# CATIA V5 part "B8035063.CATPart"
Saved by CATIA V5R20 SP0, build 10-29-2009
Part number: B8035063
Revision: 5
Definition: design
Nomenclature: B8035063
Source: made
Description: NOT SPECIFIED
Bounding box of the stored display mesh (mm): x -35 to 35, y -35 to 35, z 0 to 63
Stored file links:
  C:\Users\Utente\Desktop\3D files B803\B8035063.CATPart
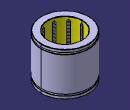
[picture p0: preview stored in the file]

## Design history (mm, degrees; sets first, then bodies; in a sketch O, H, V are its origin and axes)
Body1 "MANIFOLD_SOLID_BREP #38" (main body)
  Solid1: solid without history
Body2 "MANIFOLD_SOLID_BREP #76"
  Solid2: solid without history
Body3 "MANIFOLD_SOLID_BREP #114"
  Solid3: solid without history
Body4 "MANIFOLD_SOLID_BREP #152"
  Solid4: solid without history
Body5 "MANIFOLD_SOLID_BREP #190"
  Solid5: solid without history
Body6 "MANIFOLD_SOLID_BREP #228"
  Solid6: solid without history
Body7 "MANIFOLD_SOLID_BREP #266"
  Solid7: solid without history
Body8 "MANIFOLD_SOLID_BREP #304"
  Solid8: solid without history
Body9 "MANIFOLD_SOLID_BREP #2798"
  Solid9: solid without history
Body10 "MANIFOLD_SOLID_BREP #2836"
  Solid10: solid without history
Body11 "MANIFOLD_SOLID_BREP #2874"
  Solid11: solid without history
Body12 "MANIFOLD_SOLID_BREP #2912"
  Solid12: solid without history
Body13 "MANIFOLD_SOLID_BREP #2950"
  Solid13: solid without history
Body14 "MANIFOLD_SOLID_BREP #2988"
  Solid14: solid without history
Body15 "MANIFOLD_SOLID_BREP #3026"
  Solid15: solid without history
Body16 "MANIFOLD_SOLID_BREP #3064"
  Solid16: solid without history
Body17 "MANIFOLD_SOLID_BREP #3102"
  Solid17: solid without history
Body18 "MANIFOLD_SOLID_BREP #3140"
  Solid18: solid without history
Body19 "MANIFOLD_SOLID_BREP #3178"
  Solid19: solid without history
Body20 "MANIFOLD_SOLID_BREP #3216"
  Solid20: solid without history
Body21 "MANIFOLD_SOLID_BREP #3254"
  Solid21: solid without history
Body22 "MANIFOLD_SOLID_BREP #3292"
  Solid22: solid without history
Body23 "MANIFOLD_SOLID_BREP #3330"
  Solid23: solid without history
Body24 "MANIFOLD_SOLID_BREP #3368"
  Solid24: solid without history
Body25 "MANIFOLD_SOLID_BREP #3406"
  Solid25: solid without history
Body26 "MANIFOLD_SOLID_BREP #3444"
  Solid26: solid without history
Body27 "MANIFOLD_SOLID_BREP #3482"
  Solid27: solid without history
Body28 "MANIFOLD_SOLID_BREP #3520"
  Solid28: solid without history
Body29 "MANIFOLD_SOLID_BREP #3558"
  Solid29: solid without history
Body30 "MANIFOLD_SOLID_BREP #3596"
  Solid30: solid without history
Body31 "MANIFOLD_SOLID_BREP #3634"
  Solid31: solid without history
Body32 "MANIFOLD_SOLID_BREP #3672"
  Solid32: solid without history
Body33 "MANIFOLD_SOLID_BREP #3710"
  Solid33: solid without history
Body34 "MANIFOLD_SOLID_BREP #3748"
  Solid34: solid without history
Body35 "MANIFOLD_SOLID_BREP #3786"
  Solid35: solid without history
Body36 "MANIFOLD_SOLID_BREP #3824"
  Solid36: solid without history
Body37 "MANIFOLD_SOLID_BREP #3862"
  Solid37: solid without history
Body38 "MANIFOLD_SOLID_BREP #3900"
  Solid38: solid without history
Body39 "MANIFOLD_SOLID_BREP #3938"
  Solid39: solid without history
Body40 "MANIFOLD_SOLID_BREP #3976"
  Solid40: solid without history
Body41 "MANIFOLD_SOLID_BREP #4014"
  Solid41: solid without history
Body42 "MANIFOLD_SOLID_BREP #4052"
  Solid42: solid without history
Body43 "MANIFOLD_SOLID_BREP #4090"
  Solid43: solid without history
Body44 "MANIFOLD_SOLID_BREP #4128"
  Solid44: solid without history
Body45 "MANIFOLD_SOLID_BREP #4166"
  Solid45: solid without history
Body46 "MANIFOLD_SOLID_BREP #4204"
  Solid46: solid without history
Body47 "MANIFOLD_SOLID_BREP #4242"
  Solid47: solid without history
Body48 "MANIFOLD_SOLID_BREP #4280"
  Solid48: solid without history
Body49 "MANIFOLD_SOLID_BREP #4318"
  Solid49: solid without history
Body50 "MANIFOLD_SOLID_BREP #4356"
  Solid50: solid without history
Body51 "MANIFOLD_SOLID_BREP #4394"
  Solid51: solid without history
Body52 "MANIFOLD_SOLID_BREP #4432"
  Solid52: solid without history
Body53 "MANIFOLD_SOLID_BREP #4470"
  Solid53: solid without history
Body54 "MANIFOLD_SOLID_BREP #4508"
  Solid54: solid without history
Body55 "MANIFOLD_SOLID_BREP #4546"
  Solid55: solid without history
Body56 "MANIFOLD_SOLID_BREP #4584"
  Solid56: solid without history
Body57 "MANIFOLD_SOLID_BREP #4622"
  Solid57: solid without history
Body58 "MANIFOLD_SOLID_BREP #4660"
  Solid58: solid without history
Body59 "MANIFOLD_SOLID_BREP #4698"
  Solid59: solid without history
Body60 "MANIFOLD_SOLID_BREP #4736"
  Solid60: solid without history
Body61 "MANIFOLD_SOLID_BREP #4774"
  Solid61: solid without history
Body62 "MANIFOLD_SOLID_BREP #4812"
  Solid62: solid without history
Body63 "MANIFOLD_SOLID_BREP #4850"
  Solid63: solid without history
Body64 "MANIFOLD_SOLID_BREP #4888"
  Solid64: solid without history
Body65 "MANIFOLD_SOLID_BREP #4926"
  Solid65: solid without history
Body66 "MANIFOLD_SOLID_BREP #4964"
  Solid66: solid without history
Body67 "MANIFOLD_SOLID_BREP #5002"
  Solid67: solid without history
Body68 "MANIFOLD_SOLID_BREP #5040"
  Solid68: solid without history
Body69 "MANIFOLD_SOLID_BREP #5078"
  Solid69: solid without history
Body70 "MANIFOLD_SOLID_BREP #5116"
  Solid70: solid without history
Body71 "MANIFOLD_SOLID_BREP #5154"
  Solid71: solid without history
Body72 "MANIFOLD_SOLID_BREP #5192"
  Solid72: solid without history
Body73 "MANIFOLD_SOLID_BREP #5230"
  Solid73: solid without history
Body74 "MANIFOLD_SOLID_BREP #5268"
  Solid74: solid without history
Body75 "MANIFOLD_SOLID_BREP #5306"
  Solid75: solid without history
Body76 "MANIFOLD_SOLID_BREP #5344"
  Solid76: solid without history
Body77 "MANIFOLD_SOLID_BREP #5382"
  Solid77: solid without history
Body78 "MANIFOLD_SOLID_BREP #5420"
  Solid78: solid without history
Body79 "MANIFOLD_SOLID_BREP #5458"
  Solid79: solid without history
Body80 "MANIFOLD_SOLID_BREP #5496"
  Solid80: solid without history
Body81 "MANIFOLD_SOLID_BREP #5534"
  Solid81: solid without history
Body82 "MANIFOLD_SOLID_BREP #5572"
  Solid82: solid without history
Body83 "MANIFOLD_SOLID_BREP #5610"
  Solid83: solid without history
Body84 "MANIFOLD_SOLID_BREP #5648"
  Solid84: solid without history
Body85 "MANIFOLD_SOLID_BREP #5686"
  Solid85: solid without history
Body86 "MANIFOLD_SOLID_BREP #5724"
  Solid86: solid without history
Body87 "MANIFOLD_SOLID_BREP #5762"
  Solid87: solid without history
Body88 "MANIFOLD_SOLID_BREP #5800"
  Solid88: solid without history
Body89 "MANIFOLD_SOLID_BREP #5838"
  Solid89: solid without history
Body90 "MANIFOLD_SOLID_BREP #5876"
  Solid90: solid without history
Body91 "MANIFOLD_SOLID_BREP #5914"
  Solid91: solid without history
Body92 "MANIFOLD_SOLID_BREP #5952"
  Solid92: solid without history
Body93 "MANIFOLD_SOLID_BREP #5990"
  Solid93: solid without history
Body94 "MANIFOLD_SOLID_BREP #6028"
  Solid94: solid without history
Body95 "MANIFOLD_SOLID_BREP #6066"
  Solid95: solid without history
Body96 "MANIFOLD_SOLID_BREP #6104"
  Solid96: solid without history
Body97 "MANIFOLD_SOLID_BREP #6142"
  Solid97: solid without history
Body98 "MANIFOLD_SOLID_BREP #6180"
  Solid98: solid without history
Body99 "MANIFOLD_SOLID_BREP #6218"
  Solid99: solid without history
Body100 "MANIFOLD_SOLID_BREP #6256"
  Solid100: solid without history
Body101 "MANIFOLD_SOLID_BREP #6294"
  Solid101: solid without history
Body102 "MANIFOLD_SOLID_BREP #6332"
  Solid102: solid without history
Body103 "MANIFOLD_SOLID_BREP #6370"
  Solid103: solid without history
Body104 "MANIFOLD_SOLID_BREP #6408"
  Solid104: solid without history
Body105 "MANIFOLD_SOLID_BREP #6446"
  Solid105: solid without history
Body106 "MANIFOLD_SOLID_BREP #6484"
  Solid106: solid without history
Body107 "MANIFOLD_SOLID_BREP #6522"
  Solid107: solid without history
Body108 "MANIFOLD_SOLID_BREP #6560"
  Solid108: solid without history
Body109 "MANIFOLD_SOLID_BREP #6598"
  Solid109: solid without history
Body110 "MANIFOLD_SOLID_BREP #6636"
  Solid110: solid without history
Body111 "MANIFOLD_SOLID_BREP #6674"
  Solid111: solid without history
Body112 "MANIFOLD_SOLID_BREP #6712"
  Solid112: solid without history
Body113 "MANIFOLD_SOLID_BREP #6750"
  Solid113: solid without history
Body114 "MANIFOLD_SOLID_BREP #6788"
  Solid114: solid without history
Body115 "MANIFOLD_SOLID_BREP #6826"
  Solid115: solid without history
Body116 "MANIFOLD_SOLID_BREP #6864"
  Solid116: solid without history
Body117 "MANIFOLD_SOLID_BREP #6902"
  Solid117: solid without history
Body118 "MANIFOLD_SOLID_BREP #6940"
  Solid118: solid without history
Body119 "MANIFOLD_SOLID_BREP #6978"
  Solid119: solid without history
Body120 "MANIFOLD_SOLID_BREP #7016"
  Solid120: solid without history
Body121 "MANIFOLD_SOLID_BREP #7054"
  Solid121: solid without history
Body122 "MANIFOLD_SOLID_BREP #7092"
  Solid122: solid without history
Body123 "MANIFOLD_SOLID_BREP #7130"
  Solid123: solid without history
Body124 "MANIFOLD_SOLID_BREP #7168"
  Solid124: solid without history
Body125 "MANIFOLD_SOLID_BREP #7206"
  Solid125: solid without history
Body126 "MANIFOLD_SOLID_BREP #7244"
  Solid126: solid without history
Body127 "MANIFOLD_SOLID_BREP #7282"
  Solid127: solid without history
Body128 "MANIFOLD_SOLID_BREP #7320"
  Solid128: solid without history
Body129 "MANIFOLD_SOLID_BREP #7358"
  Solid129: solid without history
Body130 "MANIFOLD_SOLID_BREP #7396"
  Solid130: solid without history
Body131 "MANIFOLD_SOLID_BREP #7434"
  Solid131: solid without history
